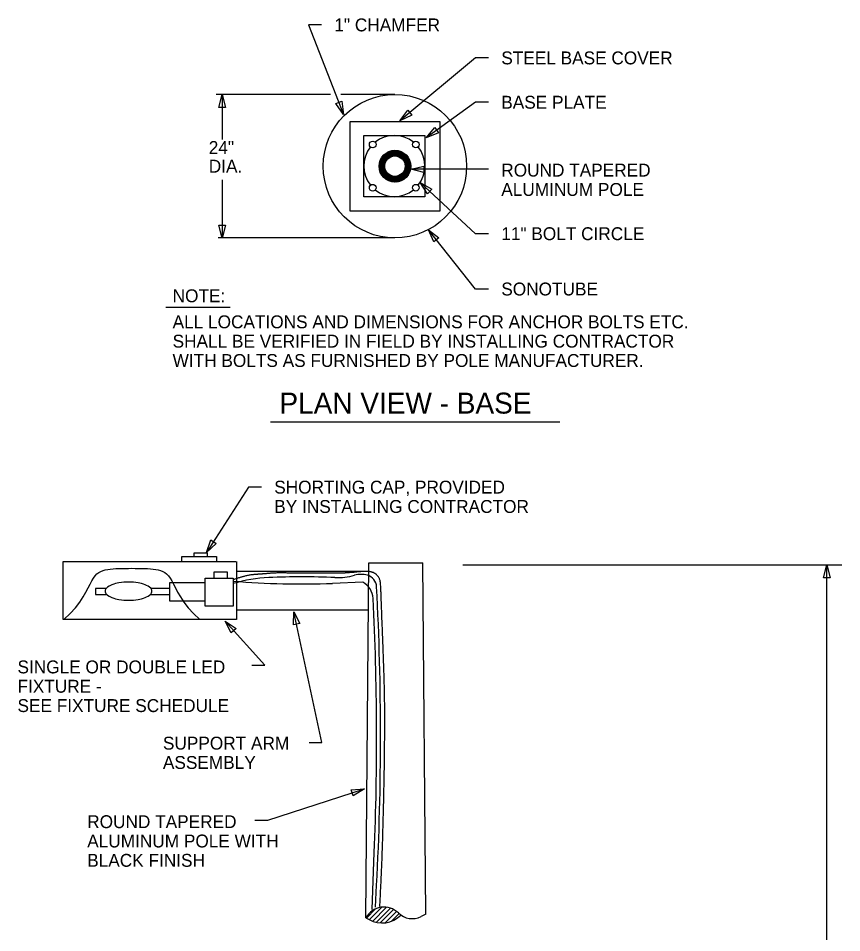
# Model space of a CAD drawing. Extents: x 10117 to 10169, y 10050 to 10161.
# Drawn here: x 10124.33 to 10166.94, y 10113.92 to 10161.22 of the extents above; entities that cross this region are included whole.
import ezdxf

# ---------------------------------------------------------------- set-up
doc = ezdxf.new("R2010")
doc.units = 0
for name, color, linetype in [('G-ANNO-TEXT', 7, 'Continuous'), ('G-DETL-LINE', 7, 'Continuous'), ('G-DETL-OTLN', 7, 'Continuous'), ('G-DETL-PATT', 7, 'Continuous')]:
    doc.layers.add(name, color=color, linetype=linetype)

msp = doc.modelspace()

# ---------------------------------------------------------------- linework, layer by layer
at = {"layer": 'G-ANNO-TEXT'}
for p, q in [((10140.016, 10160.876), (10139.349, 10160.876)), ((10139.349, 10160.876), (10141.16, 10156.247)), ((10147.985, 10159.169), (10144.072, 10155.909)), ((10148.652, 10159.169), (10147.985, 10159.169)), ((10140.488, 10157.279), (10134.574, 10157.279)), ((10134.877, 10157.271), (10134.877, 10154.947)), ((10143.817, 10157.279), (10141.025, 10157.279)), ((10147.985, 10156.878), (10145.435, 10155.039)), ((10148.652, 10156.878), (10147.985, 10156.878)), ((10147.985, 10153.407), (10144.652, 10153.407)), ((10148.652, 10153.407), (10147.985, 10153.407)), ((10134.877, 10152.865), (10134.877, 10149.847)), ((10147.985, 10150.077), (10145.116, 10152.718)), ((10147.985, 10147.216), (10145.551, 10150.28)), ((10143.817, 10149.859), (10134.671, 10149.859)), ((10148.652, 10150.077), (10147.985, 10150.077)), ((10148.652, 10147.216), (10147.985, 10147.216)), ((10131.965, 10146.272), (10135.291, 10146.272)), ((10137.383, 10140.34), (10152.345, 10140.34)), ((10136.239, 10136.96), (10134.063, 10133.594)), ((10136.905, 10136.96), (10136.239, 10136.96)), ((10147.337, 10132.951), (10166.935, 10132.951)), ((10166.163, 10113.381), (10166.163, 10132.951)), ((10140.042, 10123.77), (10138.583, 10130.528)), ((10137.081, 10127.753), (10135.027, 10130.041)), ((10136.414, 10127.753), (10137.081, 10127.753)), ((10139.375, 10123.77), (10140.042, 10123.77)), ((10137.237, 10119.75), (10142.238, 10121.363)), ((10136.57, 10119.75), (10137.237, 10119.75))]:
    msp.add_line(p, q, dxfattribs=at)
for points in [[(10134.71, 10156.604), (10134.877, 10157.271), (10135.044, 10156.604)], [(10141.072, 10156.929), (10141.16, 10156.247), (10140.762, 10156.807)], [(10144.691, 10156.208), (10144.072, 10155.909), (10144.478, 10156.464)], [(10146.073, 10155.294), (10145.435, 10155.039), (10145.878, 10155.564)], [(10145.319, 10153.24), (10144.652, 10153.407), (10145.319, 10153.574)], [(10145.494, 10152.143), (10145.116, 10152.718), (10145.72, 10152.389)], [(10135.044, 10150.514), (10134.877, 10149.847), (10134.71, 10150.514)], [(10145.835, 10149.655), (10145.551, 10150.28), (10146.096, 10149.862)], [(10134.565, 10134.063), (10134.063, 10133.594), (10134.285, 10134.244)], [(10165.996, 10132.284), (10166.163, 10132.951), (10166.329, 10132.284)], [(10138.561, 10129.841), (10138.583, 10130.528), (10138.887, 10129.912)], [(10135.348, 10129.433), (10135.027, 10130.041), (10135.596, 10129.656)], [(10141.552, 10121.317), (10142.238, 10121.363), (10141.654, 10120.999)]]:
    msp.add_lwpolyline(points, close=True, dxfattribs=at)
at = {"layer": 'G-DETL-LINE'}
for p, q in [((10142.202, 10151.993), (10142.202, 10155.158)), ((10142.202, 10155.158), (10145.366, 10155.158)), ((10145.366, 10155.158), (10145.366, 10151.993)), ((10145.366, 10151.993), (10142.202, 10151.993)), ((10134.005, 10130.815), (10134.005, 10132.264)), ((10134.005, 10132.264), (10135.453, 10132.264)), ((10135.15, 10132.567), (10134.443, 10132.567)), ((10134.443, 10132.567), (10134.443, 10132.264)), ((10135.15, 10132.264), (10135.15, 10132.567)), ((10135.453, 10132.264), (10135.453, 10130.815)), ((10128.314, 10131.725), (10128.314, 10131.422)), ((10128.869, 10131.725), (10128.314, 10131.725)), ((10132.119, 10131.725), (10131.194, 10131.725)), ((10134.005, 10132.028), (10132.153, 10132.028)), ((10132.153, 10132.028), (10132.153, 10131.085)), ((10128.314, 10131.422), (10128.904, 10131.422)), ((10131.159, 10131.422), (10132.153, 10131.422)), ((10132.153, 10131.085), (10134.005, 10131.085)), ((10135.453, 10130.815), (10134.005, 10130.815))]:
    msp.add_line(p, q, dxfattribs=at)
for points in [[(10126.686, 10130.127), (10127.008, 10130.429), (10127.286, 10130.734), (10127.509, 10131.021), (10127.687, 10131.289), (10127.828, 10131.535), (10127.942, 10131.758), (10128.038, 10131.956), (10128.126, 10132.126), (10128.214, 10132.27), (10128.305, 10132.387), (10128.399, 10132.481), (10128.497, 10132.556), (10128.601, 10132.613), (10128.711, 10132.657), (10128.828, 10132.689), (10128.954, 10132.713), (10129.089, 10132.732), (10129.232, 10132.746), (10129.383, 10132.756), (10129.539, 10132.763), (10129.7, 10132.767), (10129.865, 10132.769), (10130.032, 10132.769), (10130.2, 10132.77), (10130.368, 10132.769), (10130.535, 10132.769), (10130.7, 10132.767), (10130.861, 10132.763), (10131.017, 10132.756), (10131.168, 10132.746), (10131.311, 10132.732), (10131.446, 10132.713), (10131.572, 10132.689), (10131.689, 10132.657), (10131.799, 10132.613), (10131.903, 10132.556), (10132.001, 10132.481), (10132.095, 10132.387), (10132.186, 10132.27), (10132.274, 10132.126), (10132.362, 10131.956), (10132.458, 10131.758), (10132.572, 10131.535), (10132.713, 10131.289), (10132.891, 10131.021), (10133.114, 10130.734), (10133.392, 10130.429), (10133.714, 10130.127)], [(10142.15, 10132.052), (10140.59, 10131.992)], [(10142.63, 10115.125), (10142.75, 10118.066)], [(10142.81, 10115.245), (10142.87, 10116.386)]]:
    msp.add_lwpolyline(points, dxfattribs=at)
for centre, radius, start, end in [((10143.784, 10153.575), 1.582, 51.231, 128.769), ((10143.784, 10153.575), 1.582, 141.231, 218.769), ((10143.784, 10153.575), 1.582, 321.231, 38.769), ((10143.784, 10153.575), 1.582, 231.231, 308.769), ((10137.585, 10124.988), 7.31, 92.3002, 106.9546), ((10139.001, 10089.733), 42.594, 87.6998, 92.3002), ((10140.842, 10135.566), 3.277, 267.6998, 285.7289), ((10142.06, 10131.241), 1.217, 74.2711, 105.7289), ((10142.211, 10131.777), 0.66, 3.0108, 74.2711), ((10129.026, 10131.59), 0.207, 133.2151, 180), ((10129.501, 10131.085), 0.9, 111.2649, 133.2151), ((10129.82, 10130.264), 1.781, 99.1575, 111.2649), ((10130.032, 10128.953), 3.108, 90, 99.1575), ((10130.032, 10128.953), 3.108, 80.8425, 90), ((10130.243, 10130.264), 1.781, 68.7351, 80.8425), ((10130.562, 10131.085), 0.9, 46.7849, 68.7351), ((10131.037, 10131.59), 0.207, 360, 46.7849), ((10138.956, 10174.448), 42.487, 265.2702, 272.2041), ((10141.688, 10131.162), 1.003, 2.8586, 62.5766), ((9996.222, 10124.099), 146.851, 356.98924, 3.01076), ((10129.026, 10131.59), 0.207, 180, 226.7849), ((10129.501, 10132.095), 0.9, 226.7849, 248.7351), ((10129.82, 10132.916), 1.781, 248.7351, 260.8425), ((10130.243, 10132.916), 1.781, 279.1575, 291.2649), ((10130.562, 10132.095), 0.9, 291.2649, 313.2151), ((10131.037, 10131.59), 0.207, 313.2151, 0), ((9997.821, 10123.978), 145.049, 357.66427, 2.85862), ((10130.032, 10134.227), 3.108, 260.8425, 270), ((10130.032, 10134.227), 3.108, 270, 279.1575)]:
    msp.add_arc(centre, radius, start, end, dxfattribs=at)
msp.add_open_spline([(10143.032, 10115.278), (10143.122, 10116.842), (10143.212, 10119.579), (10143.273, 10122.346), (10143.303, 10125.956), (10143.182, 10129.294), (10143.122, 10130.768), (10143.092, 10131.7), (10143.062, 10132.121), (10142.972, 10132.332), (10142.762, 10132.542), (10142.371, 10132.633), (10141.198, 10132.512), (10140.086, 10132.512), (10138.794, 10132.512), (10137.712, 10132.542), (10137.05, 10132.482), (10136.119, 10132.422), (10135.457, 10132.181)], degree=2, dxfattribs=at)
at = {"layer": 'G-DETL-OTLN'}
for p, q in [((10141.498, 10155.887), (10146.135, 10155.887)), ((10141.498, 10151.25), (10141.498, 10155.887)), ((10146.135, 10155.887), (10146.135, 10151.25)), ((10142.996, 10153.6), (10143.786, 10154.389)), ((10142.996, 10153.547), (10143.838, 10154.389)), ((10142.999, 10153.498), (10143.888, 10154.387)), ((10143.001, 10153.656), (10143.73, 10154.385)), ((10143.009, 10153.717), (10143.668, 10154.376)), ((10143.024, 10153.784), (10143.601, 10154.361)), ((10143.605, 10154.052), (10143.934, 10154.381)), ((10143.685, 10154.08), (10143.979, 10154.374)), ((10143.75, 10154.092), (10144.022, 10154.364)), ((10143.806, 10154.096), (10144.062, 10154.352)), ((10143.05, 10153.862), (10143.523, 10154.335)), ((10143.094, 10153.958), (10143.427, 10154.291)), ((10143.857, 10154.095), (10144.101, 10154.339)), ((10143.903, 10154.089), (10144.138, 10154.324)), ((10143.947, 10154.08), (10144.174, 10154.308)), ((10143.987, 10154.068), (10144.209, 10154.29)), ((10144.025, 10154.054), (10144.242, 10154.271)), ((10144.06, 10154.037), (10144.274, 10154.251)), ((10144.093, 10154.018), (10144.304, 10154.229)), ((10144.125, 10153.997), (10144.334, 10154.206)), ((10144.154, 10153.974), (10144.362, 10154.183)), ((10144.182, 10153.95), (10144.389, 10154.157)), ((10144.207, 10153.924), (10144.415, 10154.131)), ((10144.231, 10153.895), (10144.44, 10154.103)), ((10144.254, 10153.865), (10144.463, 10154.075)), ((10144.274, 10153.833), (10144.485, 10154.045)), ((10144.292, 10153.799), (10144.506, 10154.014)), ((10144.308, 10153.763), (10144.526, 10153.981)), ((10144.321, 10153.724), (10144.545, 10153.948)), ((10144.332, 10153.683), (10144.562, 10153.913)), ((10144.34, 10153.638), (10144.578, 10153.876)), ((10143.004, 10153.451), (10143.333, 10153.78)), ((10143.012, 10153.407), (10143.306, 10153.7)), ((10143.022, 10153.364), (10143.293, 10153.636)), ((10143.033, 10153.324), (10143.289, 10153.579)), ((10143.047, 10153.285), (10143.29, 10153.528)), ((10143.061, 10153.247), (10143.296, 10153.482)), ((10143.078, 10153.211), (10143.305, 10153.439)), ((10143.095, 10153.177), (10143.317, 10153.399)), ((10143.764, 10152.75), (10144.636, 10153.621)), ((10143.815, 10152.748), (10144.638, 10153.571)), ((10143.869, 10152.75), (10144.636, 10153.517)), ((10143.927, 10152.755), (10144.63, 10153.459)), ((10144.281, 10153.319), (10144.632, 10153.669)), ((10144.32, 10153.41), (10144.625, 10153.714)), ((10144.336, 10153.478), (10144.616, 10153.758)), ((10144.343, 10153.538), (10144.605, 10153.799)), ((10144.344, 10153.59), (10144.592, 10153.838)), ((10143.115, 10153.144), (10143.332, 10153.361)), ((10143.135, 10153.112), (10143.349, 10153.326)), ((10143.156, 10153.081), (10143.367, 10153.292)), ((10143.179, 10153.052), (10143.388, 10153.261)), ((10143.203, 10153.024), (10143.411, 10153.231)), ((10143.228, 10152.996), (10143.436, 10153.204)), ((10143.254, 10152.97), (10143.462, 10153.178)), ((10143.282, 10152.946), (10143.49, 10153.154)), ((10143.311, 10152.922), (10143.52, 10153.132)), ((10143.341, 10152.9), (10143.552, 10153.112)), ((10143.372, 10152.879), (10143.587, 10153.094)), ((10143.404, 10152.859), (10143.623, 10153.078)), ((10143.438, 10152.841), (10143.661, 10153.064)), ((10143.473, 10152.823), (10143.703, 10153.053)), ((10143.509, 10152.808), (10143.747, 10153.046)), ((10143.547, 10152.793), (10143.795, 10153.042)), ((10143.587, 10152.781), (10143.848, 10153.042)), ((10143.628, 10152.77), (10143.907, 10153.049)), ((10143.671, 10152.761), (10143.976, 10153.066)), ((10143.717, 10152.754), (10144.067, 10153.104)), ((10143.99, 10152.766), (10144.619, 10153.396)), ((10144.061, 10152.785), (10144.601, 10153.325)), ((10144.144, 10152.816), (10144.57, 10153.242)), ((10144.254, 10152.874), (10144.511, 10153.131)), ((10146.135, 10151.25), (10141.498, 10151.25)), ((10133.433, 10133.41), (10133.433, 10133.578)), ((10133.433, 10133.578), (10134.106, 10133.578)), ((10134.106, 10133.578), (10134.106, 10133.376)), ((10126.655, 10130.127), (10126.655, 10133.131)), ((10126.655, 10133.131), (10135.581, 10133.131)), ((10132.793, 10133.107), (10132.793, 10133.376)), ((10132.793, 10133.376), (10134.578, 10133.376)), ((10134.578, 10133.376), (10134.578, 10133.107)), ((10135.618, 10133.131), (10135.618, 10130.127)), ((10142.433, 10132.612), (10135.618, 10132.612)), ((10142.315, 10114.698), (10142.472, 10133.058)), ((10142.472, 10133.058), (10145.267, 10133.058)), ((10145.422, 10114.884), (10145.267, 10133.058)), ((10142.396, 10130.609), (10135.618, 10130.609)), ((10135.618, 10130.127), (10126.655, 10130.127))]:
    msp.add_line(p, q, dxfattribs=at)
for points in [[(10142.315, 10114.698), (10142.477, 10114.605)], [(10145.422, 10114.884), (10145.175, 10114.76)]]:
    msp.add_lwpolyline(points, dxfattribs=at)
for centre, radius in [((10143.817, 10153.569), 3.71), ((10142.665, 10154.694), 0.172), ((10144.903, 10154.694), 0.172), ((10143.817, 10153.569), 0.821), ((10143.817, 10153.569), 0.528), ((10142.665, 10152.457), 0.172), ((10144.903, 10152.457), 0.172)]:
    msp.add_circle(centre, radius, dxfattribs=at)
for centre, radius, start, end in [((10143.249, 10114.19), 1.063, 45.3214, 151.4652), ((10143.151, 10115.778), 1.352, 240.1471, 316.0565), ((10144.716, 10115.673), 1.022, 225.3214, 296.7246)]:
    msp.add_arc(centre, radius, start, end, dxfattribs=at)
at = {"layer": 'G-DETL-PATT'}
for p, q in [((10142.343, 10114.684), (10142.815, 10115.157)), ((10142.505, 10114.604), (10143.128, 10115.228)), ((10142.667, 10114.525), (10143.37, 10115.227)), ((10142.856, 10114.471), (10143.568, 10115.184)), ((10143.058, 10114.432), (10143.749, 10115.123)), ((10143.303, 10114.435), (10143.894, 10115.026)), ((10143.618, 10114.508), (10144.031, 10114.92))]:
    msp.add_line(p, q, dxfattribs=at)

# ---------------------------------------------------------------- texts
at = {"layer": 'G-ANNO-TEXT'}
for s, height, p in [('1" CHAMFER', 0.6667, (10140.682, 10160.543)), ('STEEL BASE COVER', 0.66667, (10149.319, 10158.836)), ('BASE PLATE', 0.6667, (10149.319, 10156.544)), ('24"', 0.6667, (10134.184, 10154.202)), ('DIA.', 0.6667, (10134.184, 10153.236)), ('ROUND TAPERED ', 0.66667, (10149.319, 10153.032)), ('ALUMINUM POLE ', 0.66667, (10149.319, 10152.032)), ('11" BOLT CIRCLE', 0.66667, (10149.319, 10149.744)), ('SONOTUBE', 0.6667, (10149.319, 10146.883)), ('NOTE:', 0.6667, (10132.312, 10146.533)), ('ALL LOCATIONS AND DIMENSIONS FOR ANCHOR BOLTS ETC.', 0.66667, (10132.312, 10145.186)), ('SHALL BE VERIFIED IN FIELD BY INSTALLING CONTRACTOR', 0.66667, (10132.312, 10144.186)), ('WITH BOLTS AS FURNISHED BY POLE MANUFACTURER.', 0.66667, (10132.312, 10143.186)), ('PLAN VIEW - BASE', 1.08333, (10137.84, 10140.773)), ('SHORTING CAP, PROVIDED', 0.66667, (10137.572, 10136.636)), ('BY INSTALLING CONTRACTOR', 0.66667, (10137.572, 10135.636)), ('SINGLE OR DOUBLE LED', 0.66667, (10124.286, 10127.337)), ('FIXTURE -', 0.6667, (10124.286, 10126.337)), ('SEE FIXTURE SCHEDULE', 0.66667, (10124.286, 10125.337)), ('SUPPORT ARM', 0.66667, (10131.811, 10123.395)), ('ASSEMBLY', 0.6667, (10131.811, 10122.395)), ('ROUND TAPERED', 0.66667, (10127.893, 10119.333)), ('ALUMINUM POLE WITH', 0.66667, (10127.893, 10118.333)), ('BLACK FINISH', 0.66667, (10127.893, 10117.333))]:
    msp.add_text(s, height=height, dxfattribs=at).set_placement(p)

doc.saveas('drawing.dxf')
